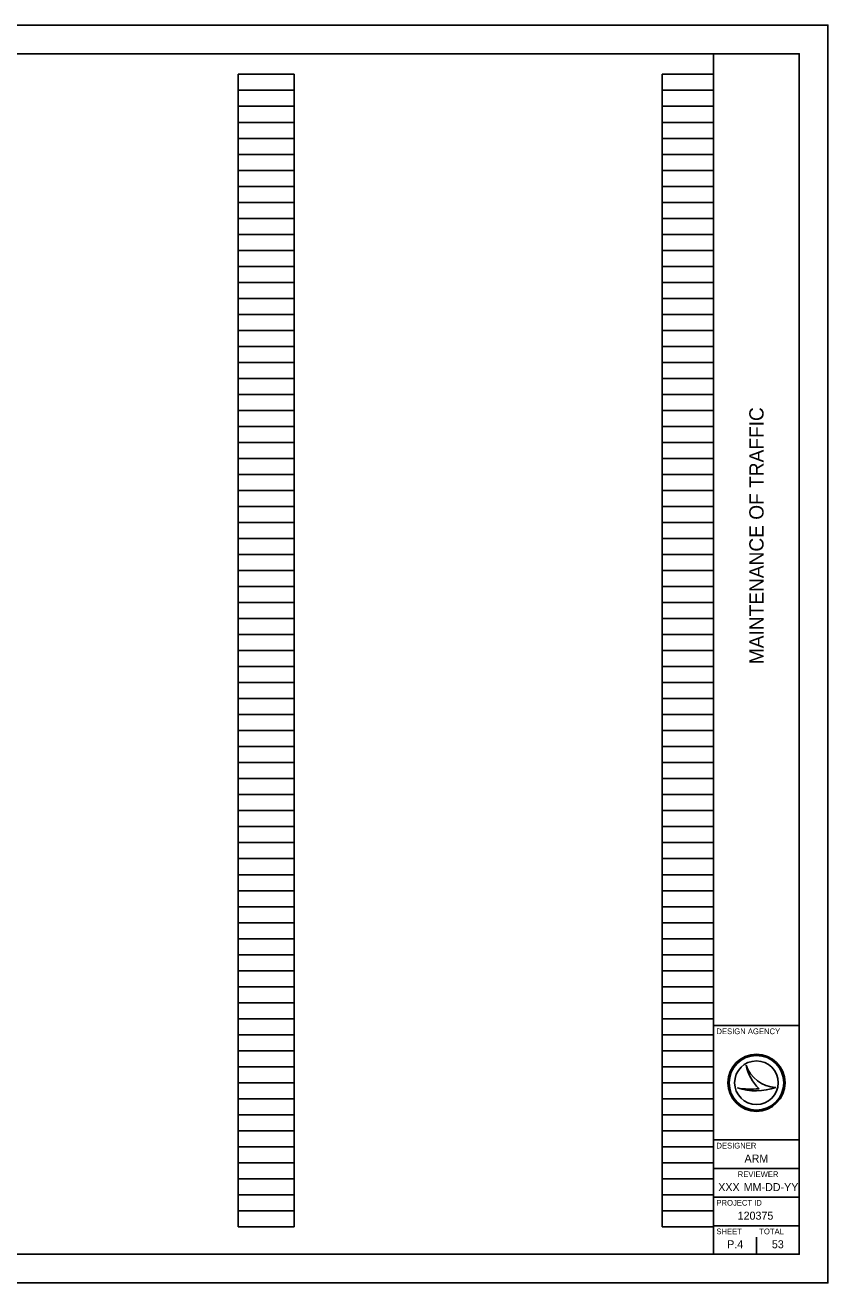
# Model space of a CAD drawing. Extents: x 0 to 34, y -2.1 to 22.
# Drawn here: x 19.95 to 34, y 0 to 22 of the extents above; entities that cross this region are included whole.
import ezdxf

# ---------------------------------------------------------------- set-up
doc = ezdxf.new("R2010")
doc.units = 0
for name, color, linetype in [('SH_Border', 7, 'Continuous'), ('SH_Cut_Line', 7, 'Continuous'), ('SH_Data', 7, 'Continuous')]:
    doc.layers.add(name, color=color, linetype=linetype)

msp = doc.modelspace()

# ---------------------------------------------------------------- linework, layer by layer
at = {"layer": 'SH_Border'}
for p, q in [((32, 0.5), (32, 21.5)), ((32, 4.5), (33.5, 4.5)), ((32, 2.5), (33.5, 2.5)), ((32, 2), (33.5, 2)), ((32, 1.5), (33.5, 1.5)), ((32, 1), (33.5, 1))]:
    msp.add_line(p, q, dxfattribs=at)
msp.add_lwpolyline([(1.5, 21.5), (33.5, 21.5), (33.5, 0.5), (1.5, 0.5)], close=True, dxfattribs=at)
at = {"layer": 'SH_Cut_Line'}
msp.add_lwpolyline([(0, 0), (34, 0), (34, 22), (0, 22)], close=True, dxfattribs=at)
at = {"layer": 'SH_Data'}
for p, q in [((23.68, 0.98), (23.68, 21.14)), ((23.68, 21.14), (24.66, 21.14)), ((24.66, 0.98), (24.66, 21.14)), ((31.1, 0.98), (31.1, 21.14)), ((31.1, 21.14), (32, 21.14)), ((32, 0.98), (32, 21.14)), ((23.68, 20.86), (24.66, 20.86)), ((31.1, 20.86), (32, 20.86)), ((23.68, 20.58), (24.66, 20.58)), ((31.1, 20.58), (32, 20.58)), ((23.68, 20.3), (24.66, 20.3)), ((31.1, 20.3), (32, 20.3)), ((23.68, 20.02), (24.66, 20.02)), ((31.1, 20.02), (32, 20.02)), ((23.68, 19.74), (24.66, 19.74)), ((31.1, 19.74), (32, 19.74)), ((23.68, 19.46), (24.66, 19.46)), ((31.1, 19.46), (32, 19.46)), ((23.68, 19.18), (24.66, 19.18)), ((31.1, 19.18), (32, 19.18)), ((23.68, 18.9), (24.66, 18.9)), ((31.1, 18.9), (32, 18.9)), ((23.68, 18.62), (24.66, 18.62)), ((31.1, 18.62), (32, 18.62)), ((23.68, 18.34), (24.66, 18.34)), ((31.1, 18.34), (32, 18.34)), ((23.68, 18.06), (24.66, 18.06)), ((31.1, 18.06), (32, 18.06)), ((23.68, 17.78), (24.66, 17.78)), ((31.1, 17.78), (32, 17.78)), ((23.68, 17.5), (24.66, 17.5)), ((31.1, 17.5), (32, 17.5)), ((23.68, 17.22), (24.66, 17.22)), ((31.1, 17.22), (32, 17.22)), ((23.68, 16.94), (24.66, 16.94)), ((31.1, 16.94), (32, 16.94)), ((23.68, 16.66), (24.66, 16.66)), ((31.1, 16.66), (32, 16.66)), ((23.68, 16.38), (24.66, 16.38)), ((31.1, 16.38), (32, 16.38)), ((23.68, 16.1), (24.66, 16.1)), ((31.1, 16.1), (32, 16.1)), ((23.68, 15.82), (24.66, 15.82)), ((31.1, 15.82), (32, 15.82)), ((23.68, 15.54), (24.66, 15.54)), ((31.1, 15.54), (32, 15.54)), ((23.68, 15.26), (24.66, 15.26)), ((31.1, 15.26), (32, 15.26)), ((23.68, 14.98), (24.66, 14.98)), ((31.1, 14.98), (32, 14.98)), ((23.68, 14.7), (24.66, 14.7)), ((31.1, 14.7), (32, 14.7)), ((23.68, 14.42), (24.66, 14.42)), ((31.1, 14.42), (32, 14.42)), ((23.68, 14.14), (24.66, 14.14)), ((31.1, 14.14), (32, 14.14)), ((23.68, 13.86), (24.66, 13.86)), ((31.1, 13.86), (32, 13.86)), ((23.68, 13.58), (24.66, 13.58)), ((31.1, 13.58), (32, 13.58)), ((23.68, 13.3), (24.66, 13.3)), ((31.1, 13.3), (32, 13.3)), ((23.68, 13.02), (24.66, 13.02)), ((31.1, 13.02), (32, 13.02)), ((23.68, 12.74), (24.66, 12.74)), ((31.1, 12.74), (32, 12.74)), ((23.68, 12.46), (24.66, 12.46)), ((31.1, 12.46), (32, 12.46)), ((23.68, 12.18), (24.66, 12.18)), ((31.1, 12.18), (32, 12.18)), ((23.68, 11.9), (24.66, 11.9)), ((31.1, 11.9), (32, 11.9)), ((23.68, 11.62), (24.66, 11.62)), ((31.1, 11.62), (32, 11.62)), ((23.68, 11.34), (24.66, 11.34)), ((31.1, 11.34), (32, 11.34)), ((23.68, 11.06), (24.66, 11.06)), ((31.1, 11.06), (32, 11.06)), ((23.68, 10.78), (24.66, 10.78)), ((31.1, 10.78), (32, 10.78)), ((23.68, 10.5), (24.66, 10.5)), ((31.1, 10.5), (32, 10.5)), ((23.68, 10.22), (24.66, 10.22)), ((31.1, 10.22), (32, 10.22)), ((23.68, 9.94), (24.66, 9.94)), ((31.1, 9.94), (32, 9.94)), ((23.68, 9.66), (24.66, 9.66)), ((31.1, 9.66), (32, 9.66)), ((23.68, 9.38), (24.66, 9.38)), ((31.1, 9.38), (32, 9.38)), ((23.68, 9.1), (24.66, 9.1)), ((31.1, 9.1), (32, 9.1)), ((23.68, 8.82), (24.66, 8.82)), ((31.1, 8.82), (32, 8.82)), ((23.68, 8.54), (24.66, 8.54)), ((31.1, 8.54), (32, 8.54)), ((23.68, 8.26), (24.66, 8.26)), ((31.1, 8.26), (32, 8.26)), ((23.68, 7.98), (24.66, 7.98)), ((31.1, 7.98), (32, 7.98)), ((23.68, 7.7), (24.66, 7.7)), ((31.1, 7.7), (32, 7.7)), ((23.68, 7.42), (24.66, 7.42)), ((31.1, 7.42), (32, 7.42)), ((23.68, 7.14), (24.66, 7.14)), ((31.1, 7.14), (32, 7.14)), ((23.68, 6.86), (24.66, 6.86)), ((31.1, 6.86), (32, 6.86)), ((23.68, 6.58), (24.66, 6.58)), ((31.1, 6.58), (32, 6.58)), ((23.68, 6.3), (24.66, 6.3)), ((31.1, 6.3), (32, 6.3)), ((23.68, 6.02), (24.66, 6.02)), ((31.1, 6.02), (32, 6.02)), ((23.68, 5.74), (24.66, 5.74)), ((31.1, 5.74), (32, 5.74)), ((23.68, 5.46), (24.66, 5.46)), ((31.1, 5.46), (32, 5.46)), ((23.68, 5.18), (24.66, 5.18)), ((31.1, 5.18), (32, 5.18)), ((23.68, 4.9), (24.66, 4.9)), ((31.1, 4.9), (32, 4.9)), ((23.68, 4.62), (24.66, 4.62)), ((31.1, 4.62), (32, 4.62)), ((23.68, 4.34), (24.66, 4.34)), ((31.1, 4.34), (32, 4.34)), ((23.68, 4.06), (24.66, 4.06)), ((31.1, 4.06), (32, 4.06)), ((23.68, 3.78), (24.66, 3.78)), ((31.1, 3.78), (32, 3.78)), ((32.567, 3.81), (32.567, 3.81)), ((23.68, 3.5), (24.66, 3.5)), ((31.1, 3.5), (32, 3.5)), ((32.417, 3.41), (32.417, 3.41)), ((32.75, 3.5), (32.75, 3.5)), ((33.087, 3.419), (33.087, 3.419)), ((23.68, 3.22), (24.66, 3.22)), ((31.1, 3.22), (32, 3.22)), ((23.68, 2.94), (24.66, 2.94)), ((31.1, 2.94), (32, 2.94)), ((23.68, 2.66), (24.66, 2.66)), ((31.1, 2.66), (32, 2.66)), ((23.68, 2.38), (24.66, 2.38)), ((31.1, 2.38), (32, 2.38)), ((23.68, 2.1), (24.66, 2.1)), ((31.1, 2.1), (32, 2.1)), ((23.68, 1.82), (24.66, 1.82)), ((31.1, 1.82), (32, 1.82)), ((23.68, 1.54), (24.66, 1.54)), ((31.1, 1.54), (32, 1.54)), ((23.68, 1.26), (24.66, 1.26)), ((31.1, 1.26), (32, 1.26)), ((23.68, 0.98), (24.66, 0.98)), ((31.1, 0.98), (32, 0.98)), ((32.375, 0.675), (32.375, 0.675)), ((32.75, 0.5), (32.75, 0.8))]:
    msp.add_line(p, q, dxfattribs=at)
for radius in [0.5, 0.477, 0.477, 0.382]:
    msp.add_circle((32.75, 3.5), radius, dxfattribs=at)
for centre, radius, start, end in [((33.116, 3.998), 0.58, 198.9257, 198.9319), ((33.347, 3.97), 0.796, 191.6379, 191.6421), ((33.116, 3.998), 0.58, 198.9319, 267.1657), ((33.347, 3.97), 0.796, 191.6421, 226.0947), ((32.739, 4.37), 1.013, 251.4576, 290.0832), ((32.648, 4.654), 1.266, 259.4964, 259.4995), ((32.739, 4.37), 1.013, 251.4527, 251.4576), ((32.648, 4.654), 1.266, 259.4995, 276.6672)]:
    msp.add_arc(centre, radius, start, end, dxfattribs=at)

# ---------------------------------------------------------------- texts
msp.add_text('MAINTENANCE OF TRAFFIC', height=0.25, rotation=90, dxfattribs=at).set_placement((32.875, 10.822))
for s, height, p in [('DESIGN AGENCY', 0.1, (32.05, 4.35)), ('DESIGNER', 0.1, (32.05, 2.35)), ('ARM', 0.14, (32.541, 2.105)), ('REVIEWER', 0.1, (32.422, 1.85)), ('XXX', 0.14, (32.081, 1.605)), ('MM-DD-YY', 0.14, (32.527, 1.605)), ('PROJECT ID', 0.1, (32.05, 1.35)), ('120375', 0.14, (32.421, 1.105)), ('SHEET', 0.1, (32.05, 0.85)), ('TOTAL', 0.1, (32.8, 0.85)), ('P.4', 0.14, (32.237, 0.605)), ('53', 0.14, (33.02, 0.605))]:
    msp.add_text(s, height=height, dxfattribs=at).set_placement(p)

doc.saveas('drawing.dxf')
